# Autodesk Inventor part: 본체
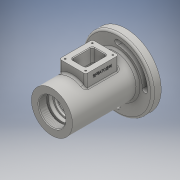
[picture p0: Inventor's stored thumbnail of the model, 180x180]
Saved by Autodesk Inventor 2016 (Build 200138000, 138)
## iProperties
Created: 2017-05
Part Number: 본체
Material: 일반
Document SubType Name: Modeling
Designer: USER
Density: 1 g/cm^3
Appearance: 기본값
Mass: 265.682 g
Surface Area: 630.775 cm^2
Volume: 265.682 cm^3
Author: USER
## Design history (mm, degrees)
sketch "스케치1"
  geometry: L1 (0, 0)-(119.064, 0); L2 (0, 31)-(99, 31); L3 (99, 31)-(99, 53); L4 (99, 53)-(112, 53); L5 (112, 53)-(112, 31); L6 (112, 31)-(115, 31); L7 (115, 31)-(115, 0); L8 (0, 31)-(0, 0)
  constraints: 16 end point, 4 perpendicular, 3 point on line, 2 horizontal, 1 vertical
  dimensions: "d0" = 62 diameter of L2 L1; "d1" = 106 diameter of L4 L1; "d2" = 115 distance between parallel lines of L7 L8; "d3" = 13 distance of L3.end L4.end; "d4" = 3 distance between parallel lines of L7 L5
revolve "회전1" sketch "스케치1" stored, may be unused: angle "d5" = 90 deg
sketch "스케치2"
  geometry: 2 further points
  constraints: 1 coincident
hole "구멍1" sketch "스케치2" at (0, 0) diameter "d6" = 40.376; stored, may be unused: countersink angle "d10" = 90 deg, drill point angle "d12" = 0 deg; dims "d7" = 12, "d8" = 4, "d9" = 2, "d11" = 12
sketch "스케치3"
  geometry: L1 (-12, -20.188)-(-12, 20.188) reference; L2 (-12, 0)-(-12, 24); L3 (-12, 24)-(-15, 24); L4 (-15, 24)-(-15, 20); L5 (-15, 20)-(-21, 20); L6 (-21, 20)-(-21, 17.5); L7 (-26, 18.5)-(-26, 17.5); L8 (-26, 17.5)-(-37, 17.5); L9 (-37, 17.5)-(-37, 26); L10 (-37, 26)-(-75, 26); L11 (-75, 26)-(-75, 17.5); L12 (-75, 17.5)-(-86, 17.5); L13 (-86, 17.5)-(-86, 16.5); L14 (-115, 31)-(-115, -31) reference; L15 (-12, 0)-(-115, 0); L16 (0, 20.188)-(0, -20.188) reference; L17 (-21, 17.5)-(-24.25, 17.5); L18 (-24.25, 17.5)-(-24.25, 18.5); L19 (-24.25, 18.5)-(-26, 18.5); L20 (-101, 16)-(-115, 22); L21 (-101, 16)-(-101, 12.5); L22 (-93.7, 10)-(-93.7, 12.5); L23 (-93.7, 12.5)-(-101, 12.5); L24 (-93.7, 10)-(-91, 10); L25 (-91, 10)-(-91, 16.5); L26 (-91, 16.5)-(-86, 16.5); L27 (-115, 22)-(-115, 0); 1 further point
  constraints: 48 end point, 12 perpendicular, 4 horizontal, 2 midpoint, 2 point on line, 2 vertical, 1 horizontal alignment
  dimensions: "d13" = 48 diameter of L3 L15; "d14" = 3 distance of L2.end L3.end; "d15" = 40 diameter of L5 L15; "d16" = 21 distance between parallel lines of L6 L16; "d18" = 26 distance between parallel lines of L7 L16; "d19" = 37 diameter of L19 L15; "d20" = 35 diameter of L17 L15; "d21" = 35 diameter of L8 L15; "d22" = 1.75 distance of L18.end L7.start; "d23" = 38 distance of L9.end L10.end; "d24" = 60 distance between parallel lines of L13 L7; "d25" = 44 diameter of L20.end L15; "d26" = 32 diameter of L20.start L15; "d27" = 14 distance between parallel lines of L14 L21; "d29" = 25 diameter of L23 L15; "d30" = 7.3 distance of L22.end L21.end; "d31" = 2.7 distance of L22.start L24.end; "d32" = 20 diameter of L24 L15; "d33" = 33 diameter of L26 L15; "d34" = 52 diameter of L10 L15; "d35" = 11 distance between parallel lines of L9 L7
revolve "회전2" sketch "스케치3" stored, may be unused: angle "d36" = 90 deg
node "작업 평면2"
sketch "스케치5"
  geometry: L1 (-31, -20)-(-81, -20); L2 (-81, -20)-(-81, 20); L3 (-81, 20)-(-31, 20); L4 (-31, 20)-(-31, -20); L5 (-56, -20)-(-56, -24); L6 (0, 31)-(0, -31) reference; 2 further points
  constraints: 10 end point, 2 midpoint, 2 parallel, 1 horizontal, 1 horizontal alignment, 1 perpendicular, 1 vertical
  dimensions: "d41" = 50 distance of L1.start L1.end; "d42" = 40 distance of L1.end L2.end; "d43" = 56 distance between parallel lines of L6 L5
extrude "돌출1" join sketch "스케치5" stored distance "d44" = 10; taper "d45" = 0 deg; dims "d13" = 48, "d14" = 3, "d15" = 40, "d16" = 21, "d18" = 26, "d19" = 37, "d20" = 35, "d21" = 35, "d22" = 1.75, "d23" = 38, "d24" = 60, "d25" = 44, "d26" = 32, "d27" = 14, "d29" = 25, "d30" = 7.3, "d31" = 2.7, "d32" = 20, "d33" = 33, "d34" = 52, "d35" = 11
sketch "스케치6"
  geometry: L1 (-40, -11)-(-72, -11); L2 (-72, -11)-(-72, 11); L3 (-72, 11)-(-40, 11); L4 (-40, 11)-(-40, -11); L5 (-31, -20)-(-81, -20) reference; 4 further points
  constraints: 8 end point, 3 midpoint, 2 parallel, 1 horizontal, 1 horizontal alignment, 1 perpendicular, 1 vertical alignment
  dimensions: "d46" = 32 distance of L1.start L1.end; "d47" = 22 distance of L1.end L2.end
extrude "돌출2" cut sketch "스케치6" distance "d48" = 50; taper "d49" = 0 deg
sketch "스케치7"
  geometry: L1 (-35.5, -15.5)-(-76.5, -15.5); L2 (-76.5, -15.5)-(-76.5, 15.5); L3 (-76.5, 15.5)-(-35.5, 15.5); L4 (-35.5, 15.5)-(-35.5, -15.5); L5 (-31, -20)-(-81, -20) reference; 8 further points
  constraints: 8 end point, 4 coincident, 3 midpoint, 2 parallel, 1 horizontal, 1 horizontal alignment, 1 perpendicular, 1 vertical alignment
  dimensions: "d50" = 41 distance of L1.start L1.end; "d51" = 31 distance of L1.end L2.end
hole "구멍2" sketch "스케치7" at (-35.5, -15.5), (-35.5, 15.5), (-76.5, 15.5), (-76.5, -15.5) diameter "d52" = 2.459; stored, may be unused: countersink angle "d56" = 90 deg, drill point angle "d58" = 118 deg; dims "d53" = 6, "d54" = 4, "d55" = 2, "d57" = 8
sketch "스케치8"
  geometry: C1 r 10 at (0, 0) reference; A1 r 4 centre (0, -41.5) between (0, -45.5) and (0, -37.5); A2 r 4 centre (-41.5, 0) between (-37.5, 0) and (-45.5, 0); A3 r 4 centre (41.5, 0) between (37.5, 0) and (45.5, 0); A4 r 4 centre (0, 41.5) between (0, 45.5) and (0, 37.5); A5 r 45.5 centre (0, 0) between (45.5, 0) and (0, 45.5); A6 r 45.5 centre (0, 0) between (-45.5, 0) and (0, -45.5); A7 r 37.5 centre (0, 0) between (37.5, 0) and (0, 37.5); A8 r 37.5 centre (0, 0) between (-37.5, 0) and (0, -37.5); 1 further point
  constraints: 16 point on circle, 8 centre point, 2 coincident
  dimensions: "d60" = 8 diameter of A1; "d61" = 8 diameter of A2; "d62" = 8 diameter of A3; "d63" = 8 diameter of A4
extrude "돌출3" cut sketch "스케치8" distance "d66" = 20; taper "d67" = 0 deg
fillet "모깎기1" dims "d71" = 3
fillet "모깎기2" dims "d72" = 3
fillet "모깎기3" dims "d73" = 3
fillet "모깎기4" dims "d74" = 3
fillet "모깎기5" dims "d75" = 3
chamfer "모따기2" distance "d76" = 0.7; stored, may be unused: second distance "d77" = 2, angle "d78" = 30 deg
fillet "모깎기6" dims "d79" = 0.3
fillet "모깎기7" dims "d80" = 0.3
chamfer "모따기3" distance "d81" = 1; stored, may be unused: second distance "d82" = 2, angle "d83" = 30 deg
fillet "모깎기8" dims "d84" = 3
chamfer "모따기4" distance "d85" = 1; stored, may be unused: second distance "d86" = 2, angle "d87" = 30 deg
chamfer "모따기5" distance "d88" = 1; stored, may be unused: second distance "d89" = 2, angle "d90" = 30 deg
sketch "스케치10"
  geometry: L1 (78, 75)-(78, 13) reference; L2 (0, 0)-(44, 0) reference; 2 further points
  constraints: 1 other
  dimensions: "d91" = 56 distance from line of point (22, 8) L1; "d92" = 8 distance from line of L2 point (22, 8)
feature "엠보싱1" sketch "스케치10" dims "d0" = 62, "d1" = 106, "d2" = 115, "d3" = 13, "d4" = 3, "d13" = 48, "d14" = 3, "d15" = 40, "d16" = 21, "d18" = 26, "d19" = 37, "d20" = 35, "d21" = 35, "d22" = 1.75, "d23" = 38, "d24" = 60, "d25" = 44, "d26" = 32, "d27" = 14, "d29" = 25, "d30" = 7.3, "d31" = 2.7, "d32" = 20, "d33" = 33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
node "솔리드1"
other parameters: "d40" = 44, "d59" = 83, "d64" = 91, "d65" = 75
